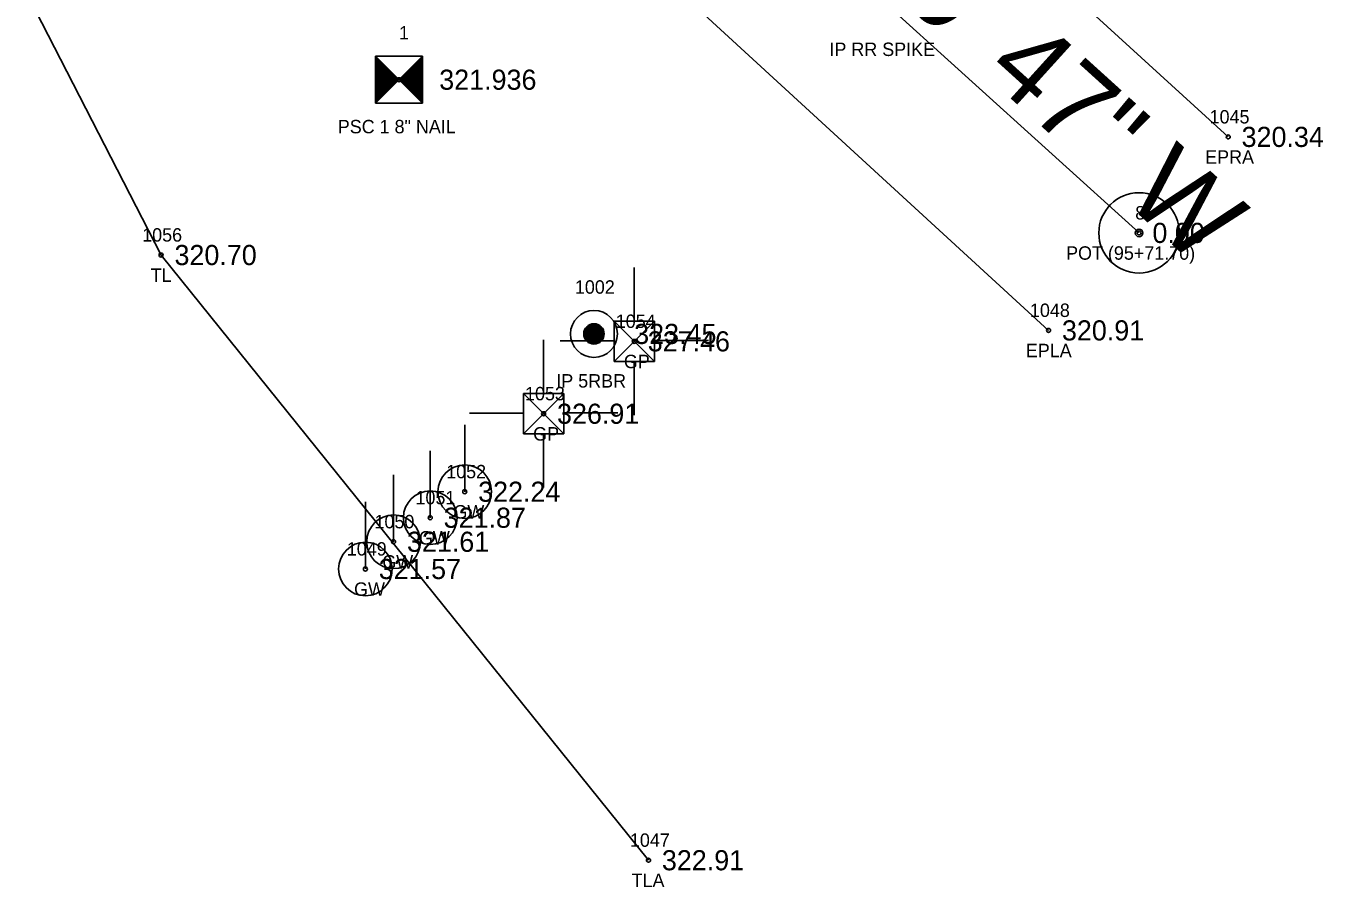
# Model space of a CAD drawing. Extents: x 1865045 to 1867370, y 910391 to 914218.
# Drawn here: x 1866724.3 to 1866821.1, y 910390.9 to 910455.2 of the extents above; entities that cross this region are included whole.
import ezdxf

# ---------------------------------------------------------------- set-up
doc = ezdxf.new("R2010")
doc.units = 0
for name, color, linetype in [('RD_EX_DV_Prop_txCode', 7, 'Continuous'), ('RD_EX_DV_PropPin', 7, 'Continuous'), ('RD_EX_Road', 7, 'Continuous'), ('RD_EX_Road_txCode', 7, 'Continuous'), ('RD_EX_TX_DV_Prop_ELEV', 7, 'Continuous'), ('RD_EX_TX_Road_ELEV', 7, 'Continuous'), ('RD_EX_TX_UT_ELEV', 7, 'Continuous'), ('RD_EX_TX_VEG_ELEV', 7, 'Continuous'), ('RD_EX_UT', 7, 'Continuous'), ('RD_EX_UT_txCode', 7, 'Continuous'), ('RD_EX_VEG', 7, 'Continuous'), ('RD_EX_VEG_txCode', 7, 'Continuous'), ('RD_HC_Cl', 7, 'Continuous'), ('RD_HC_Data', 7, 'Continuous'), ('RD_HC_Survey', 7, 'Continuous'), ('RD_HC_Survey_ELEV', 7, 'Continuous'), ('RD_HC_txCode', 7, 'Continuous'), ('RD_SMD_Locator', 7, 'Continuous')]:
    doc.layers.add(name, color=color, linetype=linetype)

msp = doc.modelspace()

# ---------------------------------------------------------------- linework, layer by layer
at = {"layer": 'RD_EX_DV_PropPin'}
for p, q in [((1866766.045, 910431.759), (1866766.045, 910432.612)), ((1866766.08, 910431.711), (1866766.08, 910432.66)), ((1866766.115, 910431.671), (1866766.115, 910432.701)), ((1866766.15, 910431.635), (1866766.15, 910432.736)), ((1866766.185, 910431.603), (1866766.185, 910432.768)), ((1866766.22, 910431.576), (1866766.22, 910432.795)), ((1866766.255, 910431.551), (1866766.255, 910432.82)), ((1866766.29, 910431.529), (1866766.29, 910432.842)), ((1866766.325, 910431.51), (1866766.325, 910432.861)), ((1866766.36, 910431.493), (1866766.36, 910432.878)), ((1866766.395, 910431.478), (1866766.395, 910432.893)), ((1866766.43, 910431.465), (1866766.43, 910432.906)), ((1866766.465, 910431.454), (1866766.465, 910432.917)), ((1866766.5, 910431.445), (1866766.5, 910432.926)), ((1866766.535, 910431.438), (1866766.535, 910432.934)), ((1866766.57, 910431.432), (1866766.57, 910432.939)), ((1866766.605, 910431.428), (1866766.605, 910432.943)), ((1866766.64, 910431.425), (1866766.64, 910432.946)), ((1866766.675, 910431.425), (1866766.675, 910432.947)), ((1866766.71, 910431.425), (1866766.71, 910432.946)), ((1866766.745, 910431.428), (1866766.745, 910432.943)), ((1866766.78, 910431.432), (1866766.78, 910432.939)), ((1866766.815, 910431.438), (1866766.815, 910432.934)), ((1866766.85, 910431.445), (1866766.85, 910432.926)), ((1866766.885, 910431.454), (1866766.885, 910432.917)), ((1866766.92, 910431.465), (1866766.92, 910432.906)), ((1866766.955, 910431.478), (1866766.955, 910432.893)), ((1866766.99, 910431.493), (1866766.99, 910432.878)), ((1866767.025, 910431.51), (1866767.025, 910432.861)), ((1866767.06, 910431.529), (1866767.06, 910432.842)), ((1866767.095, 910431.551), (1866767.095, 910432.82)), ((1866767.13, 910431.576), (1866767.13, 910432.795)), ((1866767.165, 910431.603), (1866767.165, 910432.768)), ((1866767.2, 910431.635), (1866767.2, 910432.736)), ((1866767.235, 910431.671), (1866767.235, 910432.701)), ((1866767.27, 910431.711), (1866767.27, 910432.66)), ((1866767.305, 910431.759), (1866767.305, 910432.612)), ((1866765.94, 910431.989), (1866765.94, 910432.382)), ((1866765.975, 910431.888), (1866765.975, 910432.484)), ((1866766.01, 910431.816), (1866766.01, 910432.555)), ((1866767.34, 910431.816), (1866767.34, 910432.555)), ((1866767.375, 910431.888), (1866767.375, 910432.484)), ((1866767.41, 910431.989), (1866767.41, 910432.382))]:
    msp.add_line(p, q, dxfattribs=at)
for radius in [1.75, 0.761]:
    msp.add_circle((1866766.675, 910432.186), radius, dxfattribs=at)
at = {"layer": 'RD_EX_Road'}
for points in [[(1866813.985, 910446.881), (1866778.441, 910479.305), (1866742.344, 910514.45), (1866706.867, 910550.708), (1866695.163, 910564.335), (1866672.604, 910589.75), (1866641.036, 910629.028), (1866609.698, 910670.281), (1866582.226, 910711.249), (1866556.438, 910754.585), (1866532.037, 910798.87), (1866507.56, 910846.031), (1866483.504, 910895.428), (1866461.159, 910941.957), (1866414.857, 911037.949), (1866406.114, 911034.1)], [(1866800.583, 910432.45), (1866764.321, 910465.742), (1866727.394, 910500.947), (1866691.902, 910537.684), (1866657.438, 910577.07), (1866624.972, 910617.364), (1866593.69, 910658.885), (1866565.16, 910701.476), (1866538.975, 910745.575), (1866531.335, 910758.5), (1866513.935, 910791.054), (1866489.481, 910838.441), (1866465.725, 910886.016), (1866443.471, 910933.62), (1866397.497, 911029.823), (1866406.114, 911034.1)]]:
    msp.add_lwpolyline(points, dxfattribs=at)
at = {"layer": 'RD_EX_UT'}
for p, q in [((1866769.685, 910433.132), (1866769.685, 910437.132)), ((1866771.185, 910433.132), (1866768.185, 910430.132)), ((1866768.185, 910433.132), (1866771.185, 910430.132)), ((1866771.185, 910433.132), (1866768.185, 910433.132)), ((1866768.185, 910433.132), (1866768.185, 910430.132)), ((1866771.185, 910430.132), (1866771.185, 910433.132)), ((1866762.918, 910427.734), (1866762.918, 910431.734)), ((1866768.16, 910431.68), (1866764.161, 910431.68)), ((1866771.199, 910431.698), (1866775.215, 910431.698)), ((1866768.185, 910430.132), (1866771.185, 910430.132)), ((1866769.685, 910430.132), (1866769.685, 910426.132)), ((1866764.418, 910427.734), (1866761.418, 910424.734)), ((1866761.418, 910427.734), (1866764.418, 910424.734)), ((1866764.418, 910427.734), (1866761.418, 910427.734)), ((1866761.418, 910427.734), (1866761.418, 910424.734)), ((1866764.418, 910424.734), (1866764.418, 910427.734)), ((1866761.393, 910426.282), (1866757.394, 910426.282)), ((1866764.432, 910426.3), (1866768.448, 910426.3)), ((1866757.034, 910420.418), (1866757.034, 910425.418)), ((1866761.418, 910424.734), (1866764.418, 910424.734)), ((1866762.918, 910424.734), (1866762.918, 910420.734)), ((1866754.46, 910418.479), (1866754.46, 910423.479)), ((1866751.725, 910416.686), (1866751.725, 910421.686)), ((1866749.621, 910414.654), (1866749.621, 910419.654))]:
    msp.add_line(p, q, dxfattribs=at)
for centre in [(1866757.034, 910420.418), (1866754.46, 910418.479), (1866751.725, 910416.686), (1866749.621, 910414.654)]:
    msp.add_circle(centre, 1.999, dxfattribs=at)
at = {"layer": 'RD_EX_VEG'}
msp.add_lwpolyline([(1866770.741, 910392.933), (1866734.382, 910438.071), (1866709.989, 910485.526), (1866679.017, 910526.15), (1866645.409, 910567.431), (1866612.91, 910609.636), (1866580.569, 910649.919), (1866452.858, 910898.436)], dxfattribs=at)
at = {"layer": 'RD_HC_Cl'}
msp.add_line((1866807.334, 910439.72), (1866774.184, 910469.748), dxfattribs=at)
at = {"layer": 'RD_HC_Data'}
for radius in [3, 0.282]:
    msp.add_circle((1866807.334, 910439.72), radius, dxfattribs=at)
at = {"layer": 'RD_HC_Survey'}
for p, q in [((1866750.382, 910452.898), (1866753.882, 910449.398)), ((1866753.882, 910452.898), (1866750.382, 910449.398)), ((1866750.406, 910452.873), (1866750.406, 910449.423)), ((1866750.431, 910452.849), (1866750.431, 910449.448)), ((1866750.456, 910452.824), (1866750.456, 910449.472)), ((1866750.481, 910452.799), (1866750.481, 910449.497)), ((1866750.505, 910452.774), (1866750.505, 910449.522)), ((1866750.53, 910452.75), (1866750.53, 910449.547)), ((1866750.555, 910452.725), (1866750.555, 910449.571)), ((1866750.58, 910452.7), (1866750.58, 910449.596)), ((1866750.604, 910452.675), (1866750.604, 910449.621)), ((1866750.629, 910452.651), (1866750.629, 910449.646)), ((1866750.654, 910452.626), (1866750.654, 910449.67)), ((1866750.679, 910452.601), (1866750.679, 910449.695)), ((1866750.703, 910452.576), (1866750.703, 910449.72)), ((1866750.728, 910452.552), (1866750.728, 910449.745)), ((1866750.753, 910452.527), (1866750.753, 910449.769)), ((1866750.778, 910452.502), (1866750.778, 910449.794)), ((1866750.802, 910452.477), (1866750.802, 910449.819)), ((1866750.827, 910452.453), (1866750.827, 910449.844)), ((1866750.852, 910452.428), (1866750.852, 910449.868)), ((1866750.877, 910452.403), (1866750.877, 910449.893)), ((1866750.901, 910452.378), (1866750.901, 910449.918)), ((1866750.926, 910452.354), (1866750.926, 910449.943)), ((1866750.951, 910452.329), (1866750.951, 910449.967)), ((1866750.976, 910452.304), (1866750.976, 910449.992)), ((1866751, 910452.279), (1866751, 910450.017)), ((1866751.025, 910452.255), (1866751.025, 910450.042)), ((1866751.05, 910452.23), (1866751.05, 910450.066)), ((1866751.075, 910452.205), (1866751.075, 910450.091)), ((1866751.099, 910452.18), (1866751.099, 910450.116)), ((1866751.124, 910452.156), (1866751.124, 910450.141)), ((1866751.149, 910452.131), (1866751.149, 910450.165)), ((1866751.174, 910452.106), (1866751.174, 910450.19)), ((1866751.198, 910452.081), (1866751.198, 910450.215)), ((1866751.223, 910452.057), (1866751.223, 910450.24)), ((1866751.248, 910452.032), (1866751.248, 910450.264)), ((1866751.273, 910452.007), (1866751.273, 910450.289)), ((1866751.297, 910451.982), (1866751.297, 910450.314)), ((1866751.322, 910451.958), (1866751.322, 910450.339)), ((1866751.347, 910451.933), (1866751.347, 910450.363)), ((1866752.916, 910451.933), (1866752.916, 910450.363)), ((1866752.941, 910451.958), (1866752.941, 910450.339)), ((1866752.966, 910451.982), (1866752.966, 910450.314)), ((1866752.991, 910452.007), (1866752.991, 910450.289)), ((1866753.015, 910452.032), (1866753.015, 910450.264)), ((1866753.04, 910452.057), (1866753.04, 910450.24)), ((1866753.065, 910452.081), (1866753.065, 910450.215)), ((1866753.09, 910452.106), (1866753.09, 910450.19)), ((1866753.114, 910452.131), (1866753.114, 910450.165)), ((1866753.139, 910452.156), (1866753.139, 910450.141)), ((1866753.164, 910452.18), (1866753.164, 910450.116)), ((1866753.189, 910452.205), (1866753.189, 910450.091)), ((1866753.213, 910452.23), (1866753.213, 910450.066)), ((1866753.238, 910452.255), (1866753.238, 910450.042)), ((1866753.263, 910452.279), (1866753.263, 910450.017)), ((1866753.288, 910452.304), (1866753.288, 910449.992)), ((1866753.312, 910452.329), (1866753.312, 910449.967)), ((1866753.337, 910452.354), (1866753.337, 910449.943)), ((1866753.362, 910452.378), (1866753.362, 910449.918)), ((1866753.387, 910452.403), (1866753.387, 910449.893)), ((1866753.411, 910452.428), (1866753.411, 910449.868)), ((1866753.436, 910452.453), (1866753.436, 910449.844)), ((1866753.461, 910452.477), (1866753.461, 910449.819)), ((1866753.486, 910452.502), (1866753.486, 910449.794)), ((1866753.51, 910452.527), (1866753.51, 910449.769)), ((1866753.535, 910452.552), (1866753.535, 910449.745)), ((1866753.56, 910452.576), (1866753.56, 910449.72)), ((1866753.585, 910452.601), (1866753.585, 910449.695)), ((1866753.609, 910452.626), (1866753.609, 910449.67)), ((1866753.634, 910452.651), (1866753.634, 910449.646)), ((1866753.659, 910452.675), (1866753.659, 910449.621)), ((1866753.684, 910452.7), (1866753.684, 910449.596)), ((1866753.708, 910452.725), (1866753.708, 910449.571)), ((1866753.733, 910452.75), (1866753.733, 910449.547)), ((1866753.758, 910452.774), (1866753.758, 910449.522)), ((1866753.783, 910452.799), (1866753.783, 910449.497)), ((1866753.807, 910452.824), (1866753.807, 910449.472)), ((1866753.832, 910452.849), (1866753.832, 910449.448)), ((1866753.857, 910452.873), (1866753.857, 910449.423)), ((1866751.372, 910451.908), (1866751.372, 910450.388)), ((1866751.396, 910451.883), (1866751.396, 910450.413)), ((1866751.421, 910451.859), (1866751.421, 910450.438)), ((1866751.446, 910451.834), (1866751.446, 910450.462)), ((1866751.471, 910451.809), (1866751.471, 910450.487)), ((1866751.495, 910451.784), (1866751.495, 910450.512)), ((1866751.52, 910451.76), (1866751.52, 910450.537)), ((1866751.545, 910451.735), (1866751.545, 910450.561)), ((1866751.57, 910451.71), (1866751.57, 910450.586)), ((1866751.594, 910451.685), (1866751.594, 910450.611)), ((1866751.619, 910451.661), (1866751.619, 910450.636)), ((1866751.644, 910451.636), (1866751.644, 910450.66)), ((1866751.669, 910451.611), (1866751.669, 910450.685)), ((1866751.693, 910451.586), (1866751.693, 910450.71)), ((1866751.718, 910451.562), (1866751.718, 910450.735)), ((1866751.743, 910451.537), (1866751.743, 910450.759)), ((1866751.768, 910451.512), (1866751.768, 910450.784)), ((1866751.792, 910451.487), (1866751.792, 910450.809)), ((1866751.817, 910451.463), (1866751.817, 910450.834)), ((1866751.842, 910451.438), (1866751.842, 910450.858)), ((1866751.867, 910451.413), (1866751.867, 910450.883)), ((1866751.891, 910451.388), (1866751.891, 910450.908)), ((1866751.916, 910451.364), (1866751.916, 910450.933)), ((1866751.941, 910451.339), (1866751.941, 910450.957)), ((1866751.966, 910451.314), (1866751.966, 910450.982)), ((1866751.99, 910451.289), (1866751.99, 910451.007)), ((1866752.015, 910451.265), (1866752.015, 910451.032)), ((1866752.04, 910451.24), (1866752.04, 910451.056)), ((1866752.065, 910451.215), (1866752.065, 910451.081)), ((1866752.089, 910451.19), (1866752.089, 910451.106)), ((1866752.114, 910451.166), (1866752.114, 910451.131)), ((1866752.149, 910451.166), (1866752.149, 910451.131)), ((1866752.174, 910451.19), (1866752.174, 910451.106)), ((1866752.199, 910451.215), (1866752.199, 910451.081)), ((1866752.223, 910451.24), (1866752.223, 910451.056)), ((1866752.248, 910451.265), (1866752.248, 910451.032)), ((1866752.273, 910451.289), (1866752.273, 910451.007)), ((1866752.298, 910451.314), (1866752.298, 910450.982)), ((1866752.322, 910451.339), (1866752.322, 910450.957)), ((1866752.347, 910451.364), (1866752.347, 910450.933)), ((1866752.372, 910451.388), (1866752.372, 910450.908)), ((1866752.397, 910451.413), (1866752.397, 910450.883)), ((1866752.421, 910451.438), (1866752.421, 910450.858)), ((1866752.446, 910451.463), (1866752.446, 910450.834)), ((1866752.471, 910451.487), (1866752.471, 910450.809)), ((1866752.496, 910451.512), (1866752.496, 910450.784)), ((1866752.52, 910451.537), (1866752.52, 910450.759)), ((1866752.545, 910451.562), (1866752.545, 910450.735)), ((1866752.57, 910451.586), (1866752.57, 910450.71)), ((1866752.595, 910451.611), (1866752.595, 910450.685)), ((1866752.619, 910451.636), (1866752.619, 910450.66)), ((1866752.644, 910451.661), (1866752.644, 910450.636)), ((1866752.669, 910451.685), (1866752.669, 910450.611)), ((1866752.694, 910451.71), (1866752.694, 910450.586)), ((1866752.718, 910451.735), (1866752.718, 910450.561)), ((1866752.743, 910451.76), (1866752.743, 910450.537)), ((1866752.768, 910451.784), (1866752.768, 910450.512)), ((1866752.793, 910451.809), (1866752.793, 910450.487)), ((1866752.817, 910451.834), (1866752.817, 910450.462)), ((1866752.842, 910451.859), (1866752.842, 910450.438)), ((1866752.867, 910451.883), (1866752.867, 910450.413)), ((1866752.892, 910451.908), (1866752.892, 910450.388))]:
    msp.add_line(p, q, dxfattribs=at)
msp.add_lwpolyline([(1866753.882, 910452.898), (1866750.382, 910452.898), (1866750.382, 910449.398), (1866753.882, 910449.398)], close=True, dxfattribs=at)
at = {"layer": 'RD_SMD_Locator'}
for centre in [(1866752.132, 910451.148), (1866813.985, 910446.881), (1866807.334, 910439.72), (1866734.382, 910438.071), (1866800.583, 910432.45), (1866766.675, 910432.186), (1866769.685, 910431.632), (1866762.918, 910426.234), (1866757.034, 910420.418), (1866754.46, 910418.479), (1866751.725, 910416.686), (1866749.621, 910414.654), (1866770.741, 910392.933)]:
    msp.add_circle(centre, 0.15, dxfattribs=at)

# ---------------------------------------------------------------- texts
at = {"layer": 'RD_EX_DV_Prop_txCode'}
for s, p in [('IP RR SPIKE', (1866784.239, 910452.913)), ('1002', (1866765.25, 910435.186)), ('IP 5RBR', (1866763.864, 910428.186))]:
    msp.add_text(s, height=1, dxfattribs=at).set_placement(p)
at = {"layer": 'RD_EX_Road_txCode'}
for s, p in [('1045', (1866812.599, 910447.881)), ('EPRA', (1866812.269, 910444.881)), ('1048', (1866799.197, 910433.45)), ('EPLA', (1866798.89, 910430.45))]:
    msp.add_text(s, height=1, dxfattribs=at).set_placement(p)
at = {"layer": 'RD_EX_TX_DV_Prop_ELEV'}
msp.add_text('323.45', height=1.5, dxfattribs=at).set_placement((1866769.675, 910431.436))
at = {"layer": 'RD_EX_TX_Road_ELEV'}
for s, p in [('320.34', (1866814.985, 910446.131)), ('320.91', (1866801.583, 910431.7))]:
    msp.add_text(s, height=1.5, dxfattribs=at).set_placement(p)
at = {"layer": 'RD_EX_TX_UT_ELEV'}
for s, p in [('327.46', (1866770.685, 910430.882)), ('326.91', (1866763.918, 910425.484)), ('322.24', (1866758.034, 910419.668)), ('321.87', (1866755.46, 910417.729)), ('321.61', (1866752.725, 910415.936)), ('321.57', (1866750.621, 910413.904))]:
    msp.add_text(s, height=1.5, dxfattribs=at).set_placement(p)
at = {"layer": 'RD_EX_TX_VEG_ELEV'}
for s, p in [('320.70', (1866735.382, 910437.321)), ('322.91', (1866771.741, 910392.183))]:
    msp.add_text(s, height=1.5, dxfattribs=at).set_placement(p)
at = {"layer": 'RD_EX_UT_txCode'}
for s, p in [('1054', (1866768.299, 910432.632)), ('GP', (1866768.906, 910429.632)), ('1053', (1866761.532, 910427.234)), ('GP', (1866762.138, 910424.234)), ('1052', (1866755.648, 910421.418)), ('1051', (1866753.358, 910419.479)), ('GW', (1866756.192, 910418.418)), ('1050', (1866750.3, 910417.686)), ('GW', (1866753.618, 910416.479)), ('1049', (1866748.235, 910415.654)), ('GW', (1866750.882, 910414.686)), ('GW', (1866748.778, 910412.654))]:
    msp.add_text(s, height=1, dxfattribs=at).set_placement(p)
at = {"layer": 'RD_EX_VEG_txCode'}
for s, p in [('1056', (1866732.972, 910439.071)), ('TL', (1866733.61, 910436.071)), ('1047', (1866769.355, 910393.933)), ('TLA', (1866769.481, 910390.933))]:
    msp.add_text(s, height=1, dxfattribs=at).set_placement(p)
at = {"layer": 'RD_HC_Data'}
msp.add_text('N 47%%d 49\' 47" W', height=6, rotation=317.8297, dxfattribs=at).set_placement((1866769.698, 910475.16))
at = {"layer": 'RD_HC_Survey_ELEV'}
for s, p in [('321.936', (1866755.132, 910450.398)), ('0.00', (1866808.334, 910438.97))]:
    msp.add_text(s, height=1.5, dxfattribs=at).set_placement(p)
at = {"layer": 'RD_HC_txCode'}
for s, p in [('1', (1866752.132, 910454.148)), ('PSC 1 8" NAIL', (1866747.565, 910447.148)), ('8', (1866807.051, 910440.72)), ('POT (95+71.70)', (1866801.893, 910437.72))]:
    msp.add_text(s, height=1, dxfattribs=at).set_placement(p)

doc.saveas('drawing.dxf')
